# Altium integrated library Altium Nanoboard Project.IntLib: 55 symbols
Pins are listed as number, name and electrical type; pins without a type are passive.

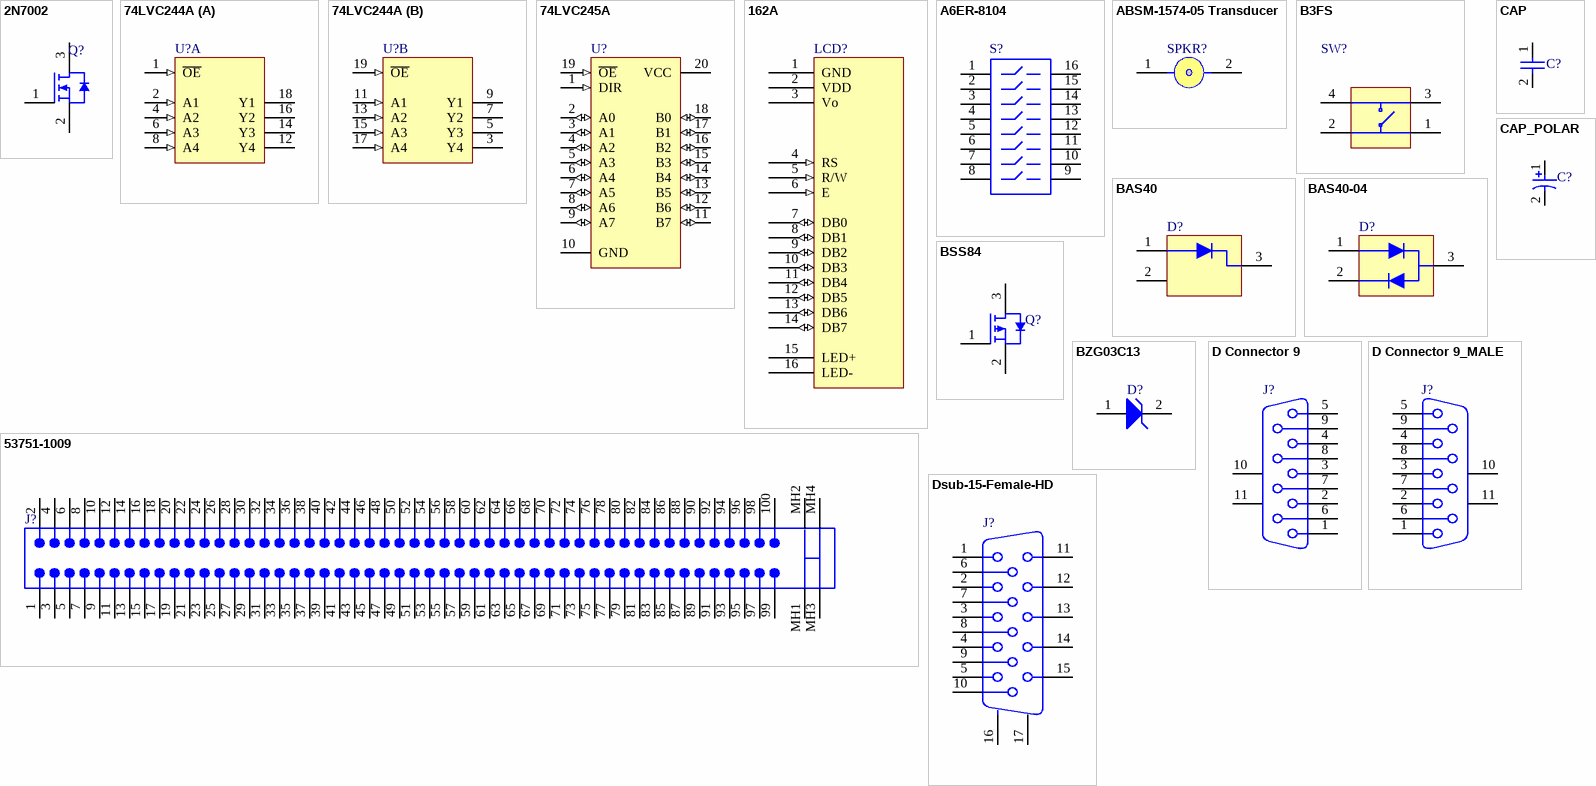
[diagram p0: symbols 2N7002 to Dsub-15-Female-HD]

## 2N7002
designator Q?
N-Channel Enhancement Mode FET
footprint SO-G3 (SOT-23; 3 Leads; 1.9mm x 2.2 mm (LxW))
pcadlib SO-G3 (SOT-23; 3 Leads; 1.9mm x 2.2 mm (LxW))
pins: 1 G "Gate", 2 S "Source", 3 D "Drain"

## 74LVC244A
designator U?
Octal Buffer/Driver with 3-State Outputs
footprint SSO-G20/P.65 (SSOP; 20 Leads; Body Width 5.3 mm; Pitch 0.65 mm)
pcadlib SSO-G20/P.65 (SSOP; 20 Leads; Body Width 5.3 mm; Pitch 0.65 mm)
pins on every part: 10 GND (power) hidden to GND, 20 VCC (power) hidden to VCC
part A pins: 1 ~{OE} (in), 2 A1 (in), 4 A2 (in), 6 A3 (in), 8 A4 (in), 12 Y4 (hiz), 14 Y3 (hiz), 16 Y2 (hiz), 18 Y1 (hiz)
part B pins: 3 Y4 (hiz), 5 Y3 (hiz), 7 Y2 (hiz), 9 Y1 (hiz), 11 A1 (in), 13 A2 (in), 15 A3 (in), 17 A4 (in), 19 ~{OE} (in)

## 74LVC245A
designator U?
Octal Bus Transceiver with 3-State Outputs
footprint SSO-G20/P.65 (SSOP; 20 Leads; Body Width 5.3 mm; Pitch 0.65 mm)
pcadlib SSO-G20/P.65 (SSOP; 20 Leads; Body Width 5.3 mm; Pitch 0.65 mm)
pins: 1 DIR (in), 2 A0 (io), 3 A1 (io), 4 A2 (io), 5 A3 (io), 6 A4 (io), 7 A5 (io), 8 A6 (io), 9 A7 (io), 10 GND (power), 11 B7 (io), 12 B6 (io), 13 B5 (io), 14 B4 (io), 15 B3 (io), 16 B2 (io), 17 B1 (io), 18 B0 (io), 19 ~{OE} (in), 20 VCC (power)

## 162A
designator LCD?
16 char * 2 line LCD character display with b/light
footprint 162A (Displaytronic, ACM 1602K Series, LCD Module)
pcadlib 162A (Displaytronic, ACM 1602K Series, LCD Module)
pins: 1 GND (power) "VSS - 0V", 2 VDD (power) "VDD - 5V", 3 Vo (hiz) "Input Voltage For LCD", 4 RS (in) "H = Data Signal, L = Instrunction Signal", 5 R/W (in) "H = Read Mode, L = Write Mode", 6 E (in) "Chip Enable (H, H->L)", 7 DB0 (io) "Chip Enable (H, H->L)", 8 DB1 (io) "Chip Enable (H, H->L)", 9 DB2 (io) "Chip Enable (H, H->L)", 10 DB3 (io) "Chip Enable (H, H->L)", 11 DB4 (io) "Chip Enable (H, H->L)", 12 DB5 (io) "Chip Enable (H, H->L)", 13 DB6 (io) "Chip Enable (H, H->L)", 14 DB7 (io) "Chip Enable (H, H->L)", 15 LED+ (power) "LED Backlight +", 16 LED- (power) "LED Backlight -"

## 53751-1009
designator J?
Board-to-Board, Docking Station, 0.80mm (.031") Pitch, Shielded Plug, Vertical, Ultra Low Profile, SMT
footprint 53751 (Board-to-Board, Docking Station, 0.80mm (.031") Pitch, Shielded Plug, Vertical, Ultra Low Profile, SMT)
pcadlib 53751 (Board-to-Board, Docking Station, 0.80mm (.031") Pitch, Shielded Plug, Vertical, Ultra Low Profile, SMT)
pins: 1, 2, 3, 4, 5, 6, 7, 8, 9, 10, 11, 12, 13, 14, 15, 16, 17, 18, 19, 20, 21, 22, 23, 24, 25, 26, 27, 28, 29, 30, 31, 32, 33, 34, 35, 36, 37, 38, 39, 40, 41, 42, 43, 44, 45, 46, 47, 48, 49, 50, 51, 52, 53, 54, 55, 56, 57, 58, 59, 60, 61, 62, 63, 64, 65, 66, 67, 68, 69, 70, 71, 72, 73, 74, 75, 76, 77, 78, 79, 80, 81, 82, 83, 84, 85, 86, 87, 88, 89, 90, 91, 92, 93, 94, 95, 96, 97, 98, 99, 100, MH1, MH2, MH2A, MH2B, MH3, MH4, MH4A, MH4B
1 alternate drawing of the same symbol

## A6ER-8104
designator S?
4009 Series DIP Switch, Raised actuator
footprint DIP-16-KEY (DIP; 16 Leads; Row Spacing 7.62 mm; Pitch 2.54 mm)
pcadlib DIP-16-KEY (DIP; 16 Leads; Row Spacing 7.62 mm; Pitch 2.54 mm)
pins: 1, 2, 3, 4, 5, 6, 7, 8, 9, 10, 11, 12, 13, 14, 15, 16

## ABSM-1574-05 Transducer
designator SPKR?
Magnetic transducer Buzzer
footprint ABSM-1574 (Surface Mount Magnetic Buzzer; Body 12.8 x 12.8 mm (LxW))
pcadlib ABSM-1574 (Surface Mount Magnetic Buzzer; Body 12.8 x 12.8 mm (LxW))
pins: 1, 1A, 2, 2A

## B3FS
designator SW?
SPNA SMD Keyboard Switch (TACT Switch)
footprint B3FS_SWITCH (Surface Mount DTSM Tact Switch; Body 6 x 6 mm (LxW))
pcadlib B3FS_SWITCH (Surface Mount DTSM Tact Switch; Body 6 x 6 mm (LxW))
pins: 1, 2, 3, 4

## BAS40
designator D?
Schottky Diode
footprint SO-G3 (SOT-23; 3 Leads; 1.9mm x 2.2 mm (LxW))
pcadlib SO-G3 (SOT-23; 3 Leads; 1.9mm x 2.2 mm (LxW))
pins: 1, 2, 3

## BAS40-04
designator D?
Dual Schottky Diode, series connected
footprint SO-G3 (SOT-23; 3 Leads; 1.9mm x 2.2 mm (LxW))
pcadlib SO-G3 (SOT-23; 3 Leads; 1.9mm x 2.2 mm (LxW))
pins: 1, 2, 3

## BSS84
designator Q?
P-Channel Enhancement Mode FET
footprint SO-G3 (SOT-23; 3 Leads; 1.9mm x 2.2 mm (LxW))
pcadlib SO-G3 (SOT-23; 3 Leads; 1.9mm x 2.2 mm (LxW))
pins: 1 G "Gate", 2 S "Source", 3 D "Drain"

## BZG03C13
designator D?
Zener Diode, 6.2V, 5W
footprint DO214 (2 C-Bend Leads; Body 4.3 x 3.6 mm (LxW))
pcadlib DO214 (2 C-Bend Leads; Body 4.3 x 3.6 mm (LxW))
pins: 1 A, 2 K

## CAP
designator C?
Capacitor, Multi Layer Ceramic
footprint CC2012-0805 (Surface Mount Capacitor; 0805 Case Size)
pcadlib CC2012-0805 (Surface Mount Capacitor; 0805 Case Size)
pins: 1, 2

## CAP_POLAR
designator C?
Capacitor, Tantalum
footprint MCCT-B (Surface Mount Chip Capacitor; Tantalum; 1.9mm x 2.2 mm (LxW))
pcadlib MCCT-B (Surface Mount Chip Capacitor; Tantalum; 1.9mm x 2.2 mm (LxW))
pins: 1, 2

## D Connector 9
designator J?
7906 Series DSUB Right Angle Socket Assembly, 9 Positions
footprint DSUB1.385-2H9 (7906 Series DSUB Right Angle Socket; Body Width, 30.81mm, 9 Positions)
pcadlib DSUB1.385-2H9 (7906 Series DSUB Right Angle Socket; Body Width, 30.81mm, 9 Positions)
pins: 1, 2, 3, 4, 5, 6, 7, 8, 9, 10 MH1, 11 MH2

## D Connector 9_MALE
designator J?
7906 Series DSUB Right Angle Plug Assembly, 9 Positions
footprint DSUB1.9_MALE (7906 Series DSUB Right Angle Plug; Body Width, 30.81mm, 9 Positions)
pcadlib DSUB1.9_MALE (7906 Series DSUB Right Angle Plug; Body Width, 30.81mm, 9 Positions)
pins: 1, 2, 3, 4, 5, 6, 7, 8, 9, 10 MH1, 11 MH2

## Dsub-15-Female-HD
designator J?
7915 Series Dsub-15 High density VGA Female connector
footprint DB15-VGA-Female (7915 Series DSUB Right Angle VGA Female connector; Body Width, 30.81mm, 15 Positions)
pcadlib DB15-VGA-Female (7915 Series DSUB Right Angle VGA Female connector; Body Width, 30.81mm, 15 Positions)
pins: 1 "Red Video", 2 "Green Video", 3 "Blue Video", 4 "Monitor ID Bit 2 (Ground)", 5 (power) "Ground", 6 (power) "Red Return (Ground)", 7 (power) "Green Return (Ground)", 8 (power) "Blue Return (Ground)", 9 "Key (not used)", 10 (power) "Sync Return (Ground)", 11 (power) "Monitor ID Bit 0 (Ground)", 12 "Monitor ID Bit 1 (Not Used)", 13 "Horizontal Zync", 14 "Vertical Sync", 15 "Vertical Sync", 16 MH1 "shield", 17 MH2 "shield"

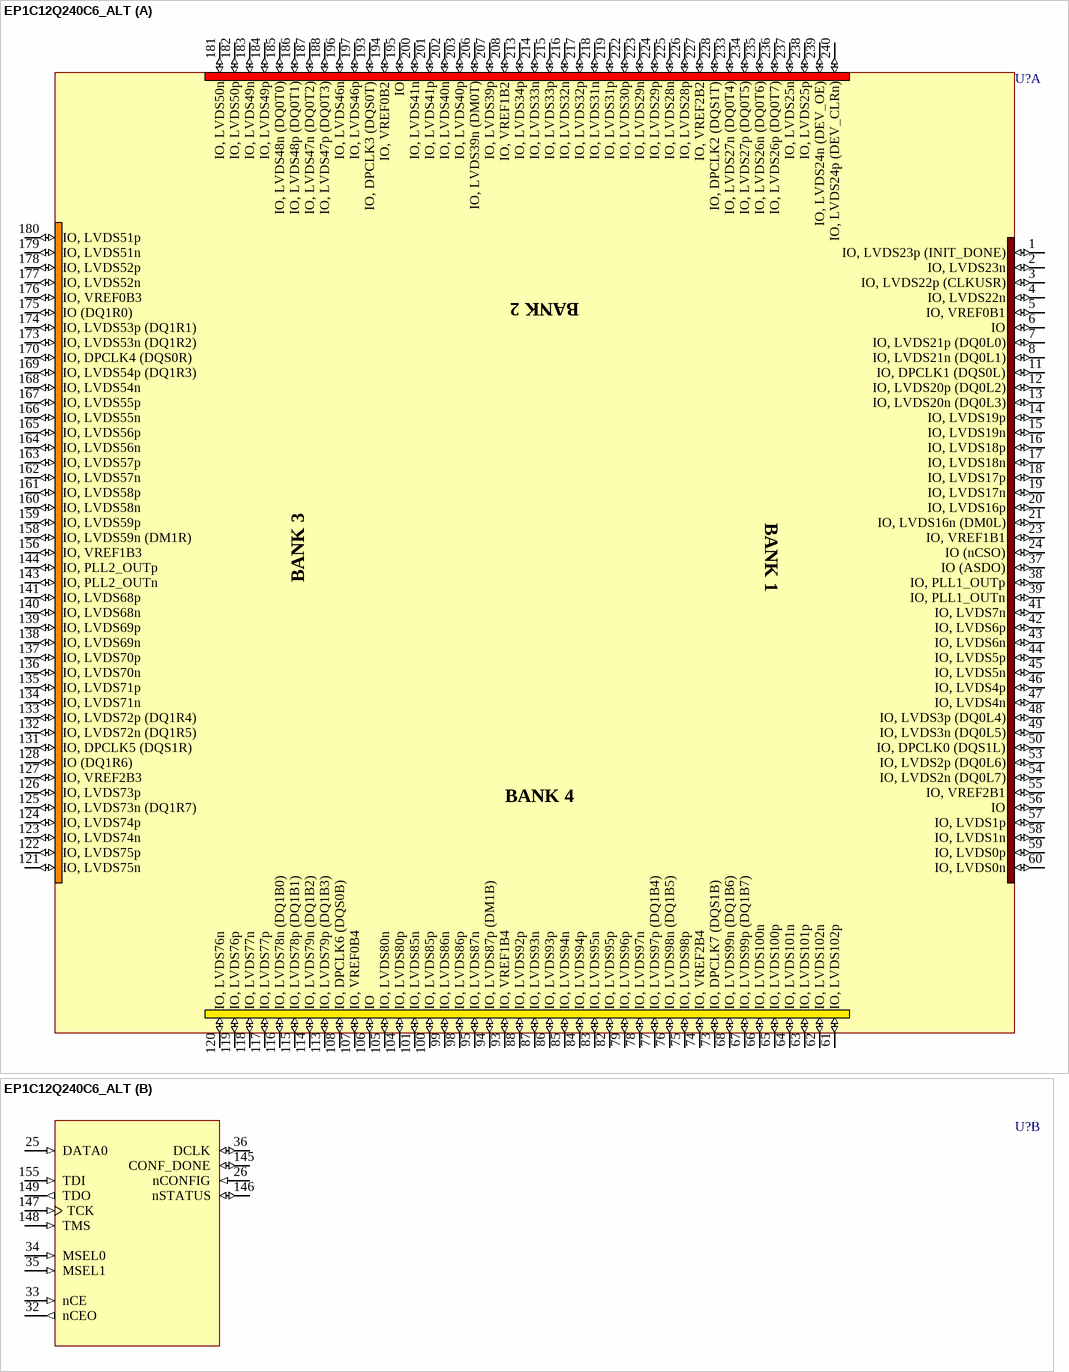
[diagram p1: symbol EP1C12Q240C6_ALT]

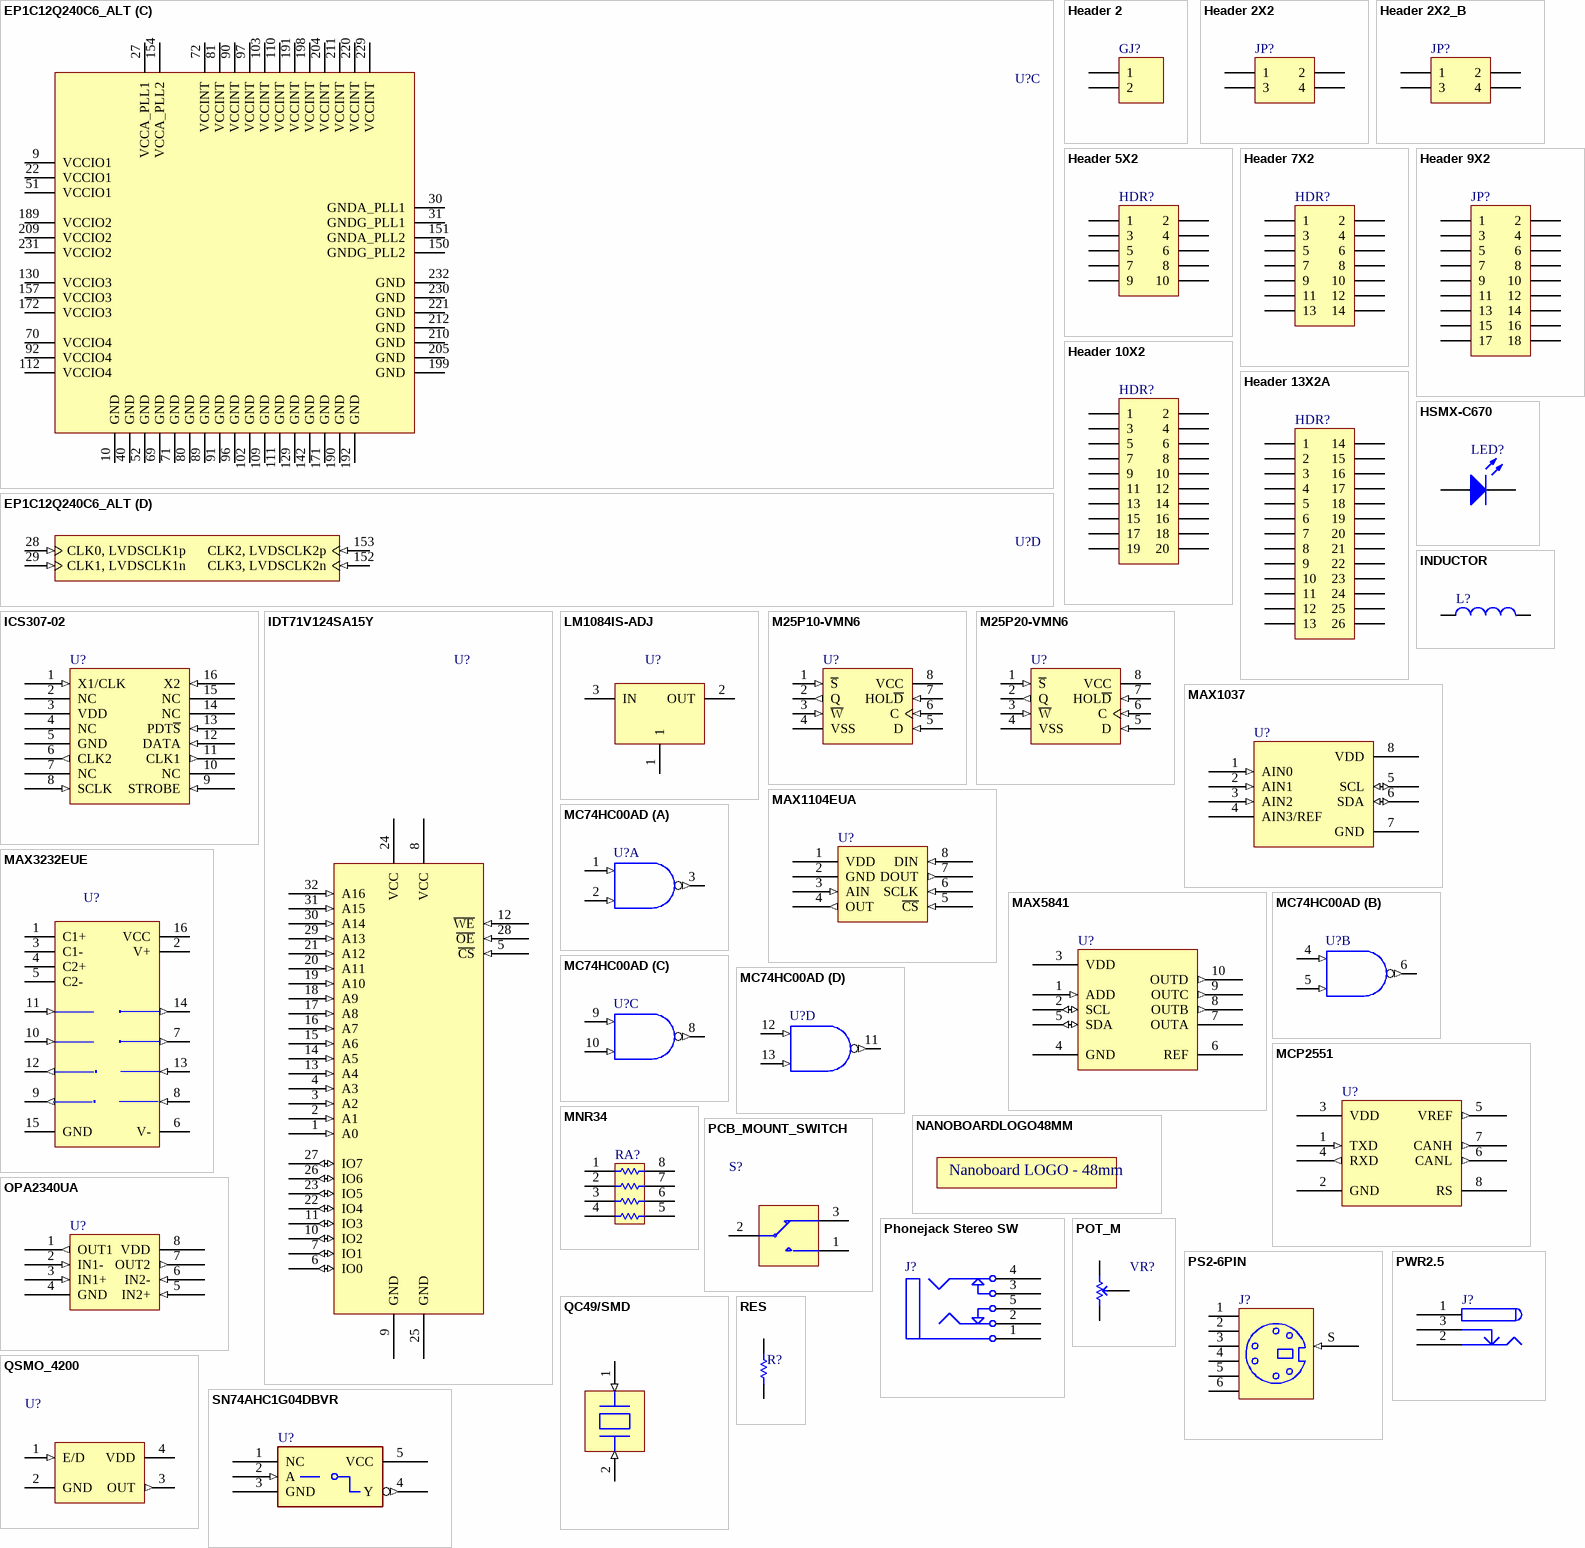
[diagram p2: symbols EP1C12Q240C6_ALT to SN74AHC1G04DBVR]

## EP1C12Q240C6_ALT
designator U?
Cyclone Family, 1.5V FPGA, 173 I/O Pins, 2 x PLLs, Commercial Grade, Speed Grade 6; PackageDocument: ver11.0, Feb-2003; Note: EP1C12Q240C6 in our IntLibs
footprint F-QFP32X32-G240/P.5N(RS) (240-Pin Plastic Quad Flat Pack (PQFP))
pcadlib F-QFP32X32-G240/P.5N(RS) (240-Pin Plastic Quad Flat Pack (PQFP))
3D model EP1C12-PQFP240 (240-Pin Plastic Quad Flat Pack (PQFP))
signal-integrity model 1c (Cyclone)
part A pins: 1 IO, LVDS23p (INIT_DONE) (io), 2 IO, LVDS23n (io), 3 IO, LVDS22p (CLKUSR) (io), 4 IO, LVDS22n (io), 5 IO, VREF0B1 (io), 6 IO (io), 7 IO, LVDS21p (DQ0L0) (io), 8 IO, LVDS21n (DQ0L1) (io), 11 IO, DPCLK1 (DQS0L) (io), 12 IO, LVDS20p (DQ0L2) (io), 13 IO, LVDS20n (DQ0L3) (io), 14 IO, LVDS19p (io), 15 IO, LVDS19n (io), 16 IO, LVDS18p (io), 17 IO, LVDS18n (io), 18 IO, LVDS17p (io), 19 IO, LVDS17n (io), 20 IO, LVDS16p (io), 21 IO, LVDS16n (DM0L) (io), 23 IO, VREF1B1 (io), 24 IO (nCSO) (io), 37 IO (ASDO) (io), 38 IO, PLL1_OUTp (io), 39 IO, PLL1_OUTn (io), 41 IO, LVDS7n (io), 42 IO, LVDS6p (io), 43 IO, LVDS6n (io), 44 IO, LVDS5p (io), 45 IO, LVDS5n (io), 46 IO, LVDS4p (io), 47 IO, LVDS4n (io), 48 IO, LVDS3p (DQ0L4) (io), 49 IO, LVDS3n (DQ0L5) (io), 50 IO, DPCLK0 (DQS1L) (io), 53 IO, LVDS2p (DQ0L6) (io), 54 IO, LVDS2n (DQ0L7) (io), 55 IO, VREF2B1 (io), 56 IO (io), 57 IO, LVDS1p (io), 58 IO, LVDS1n (io), 59 IO, LVDS0p (io), 60 IO, LVDS0n (io), 61 IO, LVDS102p (io), 62 IO, LVDS102n (io), 63 IO, LVDS101p (io), 64 IO, LVDS101n (io), 65 IO, LVDS100p (io), 66 IO, LVDS100n (io), 67 IO, LVDS99p (DQ1B7) (io), 68 IO, LVDS99n (DQ1B6) (io), 73 IO, DPCLK7 (DQS1B) (io), 74 IO, VREF2B4 (io), 75 IO, LVDS98p (io), 76 IO, LVDS98n (DQ1B5) (io), 77 IO, LVDS97p (DQ1B4) (io), 78 IO, LVDS97n (io), 79 IO, LVDS96p (io), 82 IO, LVDS95p (io), 83 IO, LVDS95n (io), 84 IO, LVDS94p (io), 85 IO, LVDS94n (io), 86 IO, LVDS93p (io), 87 IO, LVDS93n (io), 88 IO, LVDS92p (io), 93 IO, VREF1B4 (io), 94 IO, LVDS87p (DM1B) (io), 95 IO, LVDS87n (io), 98 IO, LVDS86p (io), 99 IO, LVDS86n (io), 100 IO, LVDS85p (io), 101 IO, LVDS85n (io), 104 IO, LVDS80p (io), 105 IO, LVDS80n (io), 106 IO (io), 107 IO, VREF0B4 (io), 108 IO, DPCLK6 (DQS0B) (io), 113 IO, LVDS79p (DQ1B3) (io), 114 IO, LVDS79n (DQ1B2) (io), 115 IO, LVDS78p (DQ1B1) (io), 116 IO, LVDS78n (DQ1B0) (io), 117 IO, LVDS77p (io), 118 IO, LVDS77n (io), 119 IO, LVDS76p (io), 120 IO, LVDS76n (io), 121 IO, LVDS75n (io), 122 IO, LVDS75p (io), 123 IO, LVDS74n (io), 124 IO, LVDS74p (io), 125 IO, LVDS73n (DQ1R7) (io), 126 IO, LVDS73p (io), 127 IO, VREF2B3 (io), 128 IO (DQ1R6) (io), 131 IO, DPCLK5 (DQS1R) (io), 132 IO, LVDS72n (DQ1R5) (io), 133 IO, LVDS72p (DQ1R4) (io), 134 IO, LVDS71n (io), 135 IO, LVDS71p (io), 136 IO, LVDS70n (io), 137 IO, LVDS70p (io), 138 IO, LVDS69n (io), 139 IO, LVDS69p (io), 140 IO, LVDS68n (io), 141 IO, LVDS68p (io), 143 IO, PLL2_OUTn (io), 144 IO, PLL2_OUTp (io), 156 IO, VREF1B3 (io), 158 IO, LVDS59n (DM1R) (io), 159 IO, LVDS59p (io), 160 IO, LVDS58n (io), 161 IO, LVDS58p (io), 162 IO, LVDS57n (io), 163 IO, LVDS57p (io), 164 IO, LVDS56n (io), 165 IO, LVDS56p (io), 166 IO, LVDS55n (io), 167 IO, LVDS55p (io), 168 IO, LVDS54n (io), 169 IO, LVDS54p (DQ1R3) (io), 170 IO, DPCLK4 (DQS0R) (io), 173 IO, LVDS53n (DQ1R2) (io), 174 IO, LVDS53p (DQ1R1) (io), 175 IO (DQ1R0) (io), 176 IO, VREF0B3 (io), 177 IO, LVDS52n (io), 178 IO, LVDS52p (io), 179 IO, LVDS51n (io), 180 IO, LVDS51p (io), 181 IO, LVDS50n (io), 182 IO, LVDS50p (io), 183 IO, LVDS49n (io), 184 IO, LVDS49p (io), 185 IO, LVDS48n (DQ0T0) (io), 186 IO, LVDS48p (DQ0T1) (io), 187 IO, LVDS47n (DQ0T2) (io), 188 IO, LVDS47p (DQ0T3) (io), 193 IO, DPCLK3 (DQS0T) (io), 194 IO, VREF0B2 (io), 195 IO (io), 196 IO, LVDS46n (io), 197 IO, LVDS46p (io), 200 IO, LVDS41n (io), 201 IO, LVDS41p (io), 202 IO, LVDS40n (io), 203 IO, LVDS40p (io), 206 IO, LVDS39n (DM0T) (io), 207 IO, LVDS39p (io), 208 IO, VREF1B2 (io), 213 IO, LVDS34p (io), 214 IO, LVDS33n (io), 215 IO, LVDS33p (io), 216 IO, LVDS32n (io), 217 IO, LVDS32p (io), 218 IO, LVDS31n (io), 219 IO, LVDS31p (io), 222 IO, LVDS30p (io), 223 IO, LVDS29n (io), 224 IO, LVDS29p (io), 225 IO, LVDS28n (io), 226 IO, LVDS28p (io), 227 IO, VREF2B2 (io), 228 IO, DPCLK2 (DQS1T) (io), 233 IO, LVDS27n (DQ0T4) (io), 234 IO, LVDS27p (DQ0T5) (io), 235 IO, LVDS26n (DQ0T6) (io), 236 IO, LVDS26p (DQ0T7) (io), 237 IO, LVDS25n (io), 238 IO, LVDS25p (io), 239 IO, LVDS24n (DEV_OE) (io), 240 IO, LVDS24p (DEV_CLRn) (io)
part B pins: 25 DATA0 (in), 26 nCONFIG (in), 32 nCEO (out), 33 nCE (in), 34 MSEL0 (in), 35 MSEL1 (in), 36 DCLK (io), 145 CONF_DONE (io), 146 nSTATUS (io), 147 TCK (in), 148 TMS (in), 149 TDO (out), 155 TDI (in)
part C pins: 9 VCCIO1 (power), 10 GND (power), 22 VCCIO1 (power), 27 VCCA_PLL1 (power), 30 GNDA_PLL1 (power), 31 GNDG_PLL1 (power), 40 GND (power), 51 VCCIO1 (power), 52 GND (power), 69 GND (power), 70 VCCIO4 (power), 71 GND (power), 72 VCCINT (power), 80 GND (power), 81 VCCINT (power), 89 GND (power), 90 VCCINT (power), 91 GND (power), 92 VCCIO4 (power), 96 GND (power), 97 VCCINT (power), 102 GND (power), 103 VCCINT (power), 109 GND (power), 110 VCCINT (power), 111 GND (power), 112 VCCIO4 (power), 129 GND (power), 130 VCCIO3 (power), 142 GND (power), 150 GNDG_PLL2 (power), 151 GNDA_PLL2 (power), 154 VCCA_PLL2 (power), 157 VCCIO3 (power), 171 GND (power), 172 VCCIO3 (power), 189 VCCIO2 (power), 190 GND (power), 191 VCCINT (power), 192 GND (power), 198 VCCINT (power), 199 GND (power), 204 VCCINT (power), 205 GND (power), 209 VCCIO2 (power), 210 GND (power), 211 VCCINT (power), 212 GND (power), 220 VCCINT (power), 221 GND (power), 229 VCCINT (power), 230 GND (power), 231 VCCIO2 (power), 232 GND (power)
part D pins: 28 CLK0, LVDSCLK1p (in), 29 CLK1, LVDSCLK1n (in), 152 CLK3, LVDSCLK2n (in), 153 CLK2, LVDSCLK2p (in)

## Header 2
designator GJ?
2011 Series Header, 2 Pins, 2.54mm pitch
footprint HDR1X2 (2011 Series Header, 2 Pins, 2.54mm Pitch)
pcadlib HDR1X2 (2011 Series Header, 2 Pins, 2.54mm Pitch)
pins: 1, 2

## Header 2X2
designator JP?
2011 Series Header, 4 Pins, Dual row, 2.54mil pitch
footprint HDR2X2 (2011 Series Header, 4 Pins, Dual Row, 2.54mm Pitch)
pcadlib HDR2X2 (2011 Series Header, 4 Pins, Dual Row, 2.54mm Pitch)
pins: 1, 2, 3, 4

## Header 2X2_B
designator JP?
2011 Series Header, 4 Pins, Dual row, 2.54mil pitch
footprint HDR2X2_B (2011 Series Header, 4 Pins, Dual Row, 2.54mm Pitch)
pcadlib HDR2X2_B (2011 Series Header, 4 Pins, Dual Row, 2.54mm Pitch)
pins: 1, 2, 3, 4

## Header 5X2
designator HDR?
2011 Series Header, 10 Pins, Dual row, 2.54mm pitch
footprint HDR2X5 (2011 Series Header, 10 Pins, Dual Row, 2.54mm Pitch)
pcadlib HDR2X5 (2011 Series Header, 10 Pins, Dual Row, 2.54mm Pitch)
pins: 1, 2, 3, 4, 5, 6, 7, 8, 9, 10

## Header 7X2
designator HDR?
2011 Series Header, 14 Pins, Dual row, 2.54mm pitch
footprint HDR2X7 (2011 Series Header, 14 Pins, Dual Row, 2.54mm Pitch)
pcadlib HDR2X7 (2011 Series Header, 14 Pins, Dual Row, 2.54mm Pitch)
pins: 1, 2, 3, 4, 5, 6, 7, 8, 9, 10, 11, 12, 13, 14

## Header 9X2
designator JP?
2011 Series Header, 18 Pins, Dual row, 2.54mm pitch
footprint HDR2X9 (2011 Series Header, 18 Pins, Dual Row, 2.54mm Pitch)
pcadlib HDR2X9 (2011 Series Header, 18 Pins, Dual Row, 2.54mm Pitch)
pins: 1, 2, 3, 4, 5, 6, 7, 8, 9, 10, 11, 12, 13, 14, 15, 16, 17, 18

## Header 10X2
designator HDR?
2011 Series Header, 20 Pins, Dual row, 2.54mm pitch
footprint HDR2X10 (2011 Series Header, 20 Pins, Dual Row, 2.54mm Pitch)
pcadlib HDR2X10 (2011 Series Header, 20 Pins, Dual Row, 2.54mm Pitch)
pins: 1, 2, 3, 4, 5, 6, 7, 8, 9, 10, 11, 12, 13, 14, 15, 16, 17, 18, 19, 20

## Header 13X2A
designator HDR?
3012 Series Box Header, 26 Pins, Dual Row, 2.54mm pitch, Low Profile Vertical
footprint HDR2X13_CEN_LP (3012 Series Box Header, 26 Pins, Dual Row, 2.54mm Pitch)
pcadlib HDR2X13_CEN_LP (3012 Series Box Header, 26 Pins, Dual Row, 2.54mm Pitch)
pins: 1, 2, 3, 4, 5, 6, 7, 8, 9, 10, 11, 12, 13, 14, 15, 16, 17, 18, 19, 20, 21, 22, 23, 24, 25, 26

## HSMX-C670
designator LED?
RED AS AlGaAs SMD LED
footprint SMD _LED (RED AS AlGaAs SMD LED, Body; 2mm x 1.25 mm (LxW))
pcadlib SMD _LED (RED AS AlGaAs SMD LED, Body; 2mm x 1.25 mm (LxW))
pins: 1 A, 2 K

## ICS307-02
designator U?
Serially Programmable Clock Source
footprint SO-G16 (Small Outline; 16 Leads; Body Width 3.5 mm; Pitch 1.27 mm)
pcadlib SO-G16 (Small Outline; 16 Leads; Body Width 3.5 mm; Pitch 1.27 mm)
pins: 1 X1/CLK (in) "Reference Word Devider Input", 2 NC "Reference Word Devider Input", 3 VDD (power) "Positive Supply, 3V3 or 5V", 4 NC, 5 GND (power), 6 CLK2 (out) "Fixed Clock Ref", 7 NC "Crystal connection", 8 SCLK (in) "Serial Programming Clock", 9 STROBE (in) "Serial Programming Strobe", 10 NC, 11 CLK1 (out) "Variable Clock Output", 12 DATA (in) "Serial Programming Data", 13 PDT~{S} (in) "Low = TriState CLK1 and CLK2 and Power Down", 14 NC, 15 NC, 16 X2 (in) "Crystal Terminal"

## IDT71V124SA15Y
designator U?
CMOS Static RAM, 3.3V, 128K x 8 bit
footprint SO-J32 (SOJ; 32 Leads; Body Width 7.5 mm; Pitch 1.27 mm)
pcadlib SO-J32 (SOJ; 32 Leads; Body Width 7.5 mm; Pitch 1.27 mm)
pins: 1 A0 (in) "Address 0", 2 A1 (in) "Address 1", 3 A2 (in) "Address 3", 4 A3 (in) "Address 3", 5 ~{CS} (in) "Chip Select", 6 IO0 (io) "Data 0", 7 IO1 (io) "Data 1", 8 VCC (power) "Pos Supply", 9 GND (power), 10 IO2 (io) "Data 2", 11 IO3 (io) "Data 3", 12 ~{WE} (in) "Write Enable", 13 A4 (in) "Address 4", 14 A5 (in) "Address 5", 15 A6 (in) "Address 6", 16 A7 (in) "Address 7", 17 A8 (in) "Address 8", 18 A9 (in) "Address 9", 19 A10 (in) "Address 10", 20 A11 (in) "Address 11", 21 A12 (in) "Address 12", 22 IO4 (io) "Data 4", 23 IO5 (io) "Data 5", 24 VCC (power) "Pos Supply", 25 GND (power), 26 IO6 (io) "Data 6", 27 IO7 (io) "Data 7", 28 ~{OE} (in) "Output Enable", 29 A13 (in) "Address 13", 30 A14 (in) "Address 14", 31 A15 (in) "Address 15", 32 A16 (in) "Address 16"

## INDUCTOR
designator L?
CM453232 Series Wirewound Inductor, 330uH
footprint CC4532-1812 (Surface Mount Chip Inductor; 4mm x 3.4 mm (LxW))
pcadlib CC4532-1812 (Surface Mount Chip Inductor; 4mm x 3.4 mm (LxW))
pins: 1, 2

## LM1084IS-ADJ
designator U?
5A Low Dropout Positive Regulators
footprint TO-263 (TO-263-AB; 3 Leads (1 Cropped); Body 14.35 (inc. leads) x 10.41 mm (LxW max))
pcadlib TO-263 (TO-263-AB; 3 Leads (1 Cropped); Body 14.35 (inc. leads) x 10.41 mm (LxW max))
pins: 1 "Output", 2 OUT (power) "Output", 3 IN (power) "Input"

## M25P10-VMN6
designator U?
8 Mbit, Low Voltage, Serial Flash Memory With 40 MHz SPI Bus Interface
footprint SO8_MW/SO8_MN (Small Outline; 8 Leads; Body Width 5.2 mm; Pitch 1.27 mm)
pcadlib SO8_MW/SO8_MN (Small Outline; 8 Leads; Body Width 5.2 mm; Pitch 1.27 mm)
pins: 1 ~{S} (in), 2 Q (out) "Serial Output", 3 ~{W} (in) "Serial Output", 4 VSS (power) "Serial Output", 5 D (in) "Serial Input", 6 C (in) "Serial Input", 7 HOL~{D} (in) "Serial Input", 8 VCC (power) "Serial Input"

## M25P20-VMN6
designator U?
8 Mbit, Low Voltage, Serial Flash Memory With 40 MHz SPI Bus Interface
footprint SO8_MW/SO8_MN (Small Outline; 8 Leads; Body Width 5.2 mm; Pitch 1.27 mm)
pcadlib SO8_MW/SO8_MN (Small Outline; 8 Leads; Body Width 5.2 mm; Pitch 1.27 mm)
pins: 1 ~{S} (in), 2 Q (out) "Serial Output", 3 ~{W} (in) "Serial Output", 4 VSS (power) "Serial Output", 5 D (in) "Serial Input", 6 C (in) "Serial Input", 7 HOL~{D} (in) "Serial Input", 8 VCC (power) "Serial Input"

## MAX1037
designator U?
4 Channel 8 Bit ADC, I2C interface, 2.7V to 3.6V Supply
footprint SOT23_8 (Small Outline; 8 Leads; Body 2.9 x 1.6 mm (LxW max))
pcadlib SOT23_8 (Small Outline; 8 Leads; Body 2.9 x 1.6 mm (LxW max))
pins: 1 AIN0 (in) "Analog Input 0", 2 AIN1 (in) "Analog Input 0", 3 AIN2 (in) "Analog Input 0", 4 AIN3/REF (power) "Analog Input 3/ Reference Input", 5 SCL (io) "I2C Clock Line", 6 SDA (io) "I2C Data Line", 7 GND (power), 8 VDD (power) "Positive Supply"

## MAX1104EUA
designator U?
8 bit CODEC with 4 wire logic interface
footprint TSSO3x5-G8/X.35 (Shrink Small Outline; 8 Leads; Body Width 3 mm; Pitch 0.65 mm)
pcadlib TSSO3x5-G8/X.35 (Shrink Small Outline; 8 Leads; Body Width 3 mm; Pitch 0.65 mm)
pins: 1 VDD (power) "Positive Supply 2V7 5V5", 2 GND (power), 3 AIN (in) "Analog Input", 4 OUT (out) "Analog Output", 5 ~{CS} (in) "Chip Select", 6 SCLK (in) "Serial Clock", 7 DOUT (out) "Serial Output", 8 DIN (in) "SPI Serial Input"

## MAX3232EUE
designator U?
3.0V TO 5.5V, Low-Power, up to 1Mbps, True RS-232 Transceiver Using Four 0.1µF External Capacitor
footprint SO-G16 (Small Outline; 16 Leads; Body Width 3.9 mm; Pitch 1.27 mm)
pcadlib SO-G16 (Small Outline; 16 Leads; Body Width 3.9 mm; Pitch 1.27 mm)
pins: 1 C1+, 2 V+ (power), 3 C1-, 4 C2+, 5 C2-, 6 V- (power), 7 T2OUT (out), 8 R2IN (in), 9 R2OUT (out), 10 T2IN (in), 11 T1IN (in), 12 R1OUT (out), 13 R1IN (in), 14 T1OUT (out), 15 GND (power), 16 VCC (power)

## MAX5841
designator U?
4 Channel DAC, I2C, 2.7V to 5.5V
footprint USOP10 (Shrink Small Outline; 10 Leads; Body Width 3 mm; Pitch 0.5 mm)
pcadlib USOP10 (Shrink Small Outline; 10 Leads; Body Width 3 mm; Pitch 0.5 mm)
pins: 1 ADD (in) "I2C Address Select", 2 SCL (io) "I2C Clock", 3 VDD (power) "Positive Supply 2.7V to 5.5V", 4 GND (power), 5 SDA (io) "GND", 6 REF "Reference Voltage Input 1V to VDD", 7 OUTA "DAC Output", 8 OUTB (out) "DAC Output", 9 OUTC (out) "DAC Output", 10 OUTD (out) "DAC Output"

## MC74HC00AD
designator U?
Quad 2-Input NAND Gate
footprint SO-G14/Y2.2 (Small Outline; 14 Leads; Body Width 3.9 mm; Pitch 1.27 mm)
pcadlib SO-G14/Y2.2 (Small Outline; 14 Leads; Body Width 3.9 mm; Pitch 1.27 mm)
pins on every part: 7 GND (power) hidden to GND, 14 VDD (power) hidden to VCC
part A pins: 1 A (in), 2 B (in), 3 Y (out)
part B pins: 4 A (in), 5 B (in), 6 Y (out)
part C pins: 8 Y (out), 9 A (in), 10 B (in)
part D pins: 11 Y (out), 12 A (in), 13 B (in)

## MCP2551
designator U?
High Speed Can Transceiver
footprint SOIC8 (Small Outline; 8 Leads; Body Width 3.9 mm; Pitch 1.27 mm)
pcadlib SOIC8 (Small Outline; 8 Leads; Body Width 3.9 mm; Pitch 1.27 mm)
pins: 1 TXD (in) "Screw Terminal", 2 GND (power), 3 VDD (power) "Positive Supply 4.5V to 5.5V", 4 RXD (out) "Receive Data", 5 VREF (out) "Reference Voltage", 6 CANL (out) "CAN Bus Low Line", 7 CANH (out) "CAN Bus High Line", 8 RS "Mode/Slope Setting"

## MNR34
designator RA?
Resistor Array, 8 pin, 4 Element, 100 Ohms
footprint MNR34 (Surface Mount, Chip Resistor Array; 5.2mm x 3.1 mm (LxW))
pcadlib MNR34 (Surface Mount, Chip Resistor Array; 5.2mm x 3.1 mm (LxW))
pins: 1, 2, 3, 4, 5, 6, 7, 8

## NANOBOARDLOGO48MM
designator ?  (graphical)
Altium Logo
footprint NanoBoard1_LOGO (NanoBoard Logo)
pcadlib NanoBoard1_LOGO (NanoBoard Logo)

## OPA2340UA
designator U?
Dual Operational Amplifier, Single-Supply, Rail-to-Rail
footprint SO-G8 (Small Outline; 8 Leads; Body Width 3.5 mm; Pitch 1.27 mm)
pcadlib SO-G8 (Small Outline; 8 Leads; Body Width 3.5 mm; Pitch 1.27 mm)
pins: 1 OUT1 (out), 2 IN1- (in), 3 IN1+ (in), 4 GND (power), 5 IN2+ (in), 6 IN2- (in), 7 OUT2 (out), 8 VDD (power)

## PCB_MOUNT_SWITCH
designator S?
SPDT Subminiature Toggle Switch, Right Angle Mounting, Vertical Actuation
footprint TL36WW15050 (SPDT Subminiature Toggle Switch, Right Angle Mounting, Vertical Actuation)
pcadlib TL36WW15050 (SPDT Subminiature Toggle Switch, Right Angle Mounting, Vertical Actuation)
pins: 1, 2, 3

## Phonejack Stereo SW
designator J?
3.5mm Audio Jack, Stereo
footprint ST-3150-5N (Stereo Jack, 3.5mm, 5 Position)
pcadlib ST-3150-5N (Stereo Jack, 3.5mm, 5 Position)
pins: 1, 1A, 1B, 2, 2A, 2B, 3, 3A, 3B, 4, 4A, 4B, 5, 5A, 5B

## POT_M
designator VR?
100k Ohms Square Trimming Potentiometer
footprint POT4MM-2 (Surface Mount, Square Trimming Potentiometer, Body 4.5mm x 4.5mm (LxW))
pcadlib POT4MM-2 (Surface Mount, Square Trimming Potentiometer, Body 4.5mm x 4.5mm (LxW))
pins: CCW -, CW +, W

## PS2-6PIN
designator J?
6 Pin Through Hole PS2 Socket (Kycon P/N)
footprint PS2-6PIN (PS2 Socket, 6 Pin, Through Hole)
pcadlib PS2-6PIN (PS2 Socket, 6 Pin, Through Hole)
pins: 1, 2, 3, 4, 5, 6, S (in)

## PWR2.5
designator J?
DC Power Jack, 2.5mm, KLD Series, PCB Mount
footprint KLD-0202 (DC Power Jack, 2.5mm, KLD Series, PCB Mount)
pcadlib KLD-0202 (DC Power Jack, 2.5mm, KLD Series, PCB Mount)
pins: 1 (power), 1A (power), 1B (power), 2 (power), 2A (power), 2B (power), 3 (power), 3A (power), 3B (power)

## QC49/SMD
designator CR?
Hy-Q QC49/SSMD Crystal, 20MHz
footprint QC49/SMD (Surface Mount 20MHz Crystal, 12.9mm x 4.8mm (LxW))
pcadlib QC49/SMD (Surface Mount 20MHz Crystal, 12.9mm x 4.8mm (LxW))
pins: 1 (in), 2 (in)

## QSMO_4200
designator U?
QSMO - 4200 SERIES, 40MHz, SURFACE MOUNT CRYSTAL OSCILLATOR
footprint QSMO_4200 (Surface Mount 40MHz Crystal, 7.5mm x 5mm (LxW))
pcadlib QSMO_4200 (Surface Mount 40MHz Crystal, 7.5mm x 5mm (LxW))
pins: 1 E/D (in) "Low Disables Clock", 2 GND (power), 3 OUT (out) "Output", 4 VDD (power)

## RES
designator R?
Resistor
footprint CC2012-0805 (Surface Mount Resistor; 0805 Case Size)
pcadlib CC2012-0805 (Surface Mount Resistor; 0805 Case Size)
pins: 1, 2

## SN74AHC1G04DBVR
designator U?
Single Gate Inverter
footprint SO-G5/P.95 (Small Outline; 5 Leads; Body 2 x 1.25 mm (LxW))
pcadlib SO-G5/P.95 (Small Outline; 5 Leads; Body 2 x 1.25 mm (LxW))
pins: 1 NC, 2 A (in), 3 GND (power), 4 Y (out), 5 VCC (power)

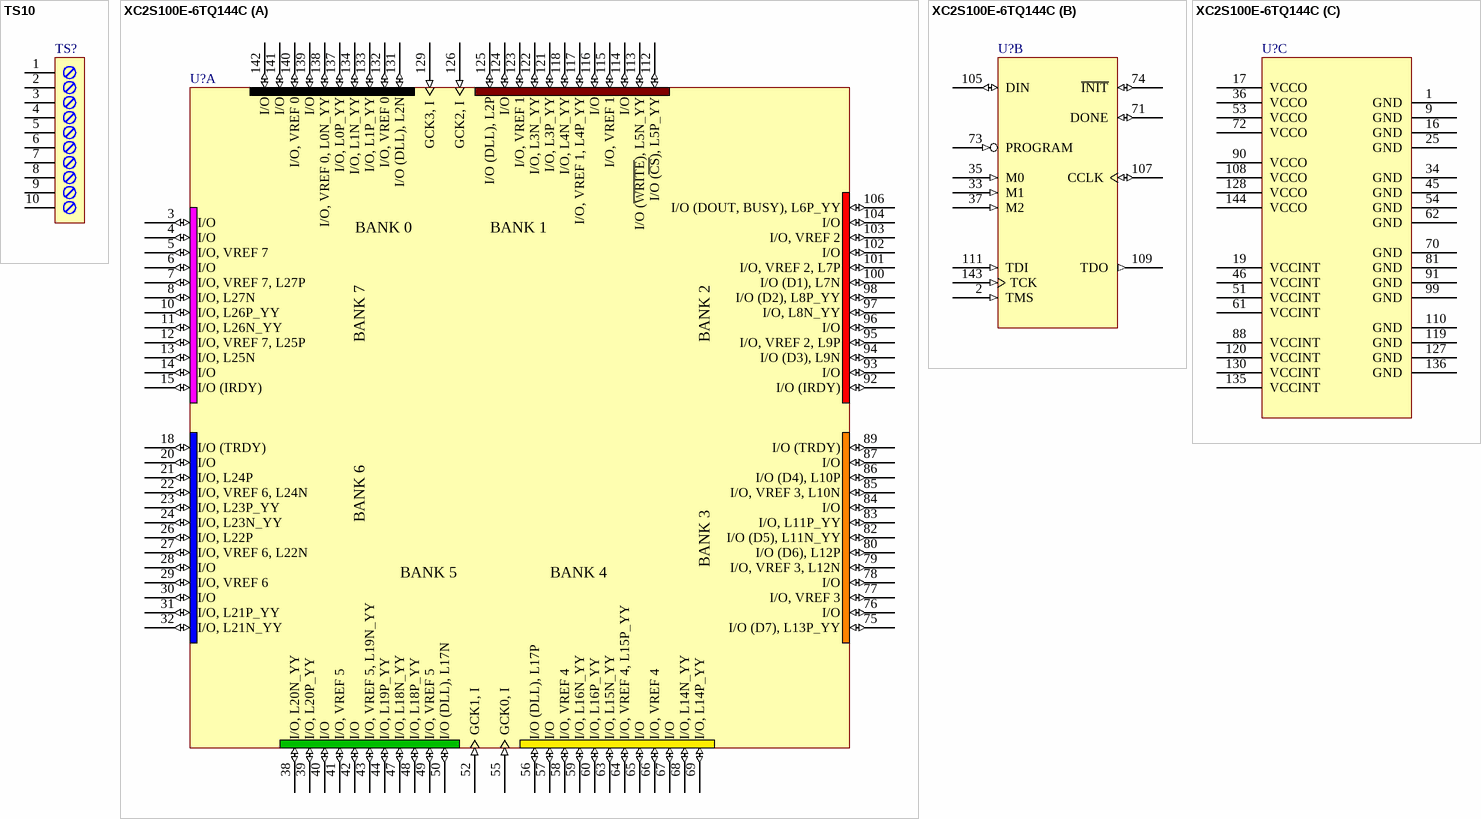
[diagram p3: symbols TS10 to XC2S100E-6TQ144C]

## TS10
designator TS?
Screw Terminal Strip, 10 Way, 2.54 mm Pitch
footprint TS2.54x10 (Screw Terminal Strip, 10 Way, 2.54 mm Pitch)
pcadlib TS2.54x10 (Screw Terminal Strip, 10 Way, 2.54 mm Pitch)
pins: 1 "Screw Terminal", 2 "Screw Terminal", 3 "Screw Terminal", 4 "Screw Terminal", 5 "Screw Terminal", 6 "Screw Terminal", 7 "Screw Terminal", 8 "Screw Terminal", 9 "Screw Terminal", 10 "Screw Terminal"

## XC2S100E-6TQ144C
designator U?
Spartan-IIE 1.8V FPGA, 144-Pin TQFP, Standard Performance, Commercial Grade
footprint TQ144 (144-Pin Thin Quad Flat Pack (TQ144))
pcadlib TQ144 (144-Pin Thin Quad Flat Pack (TQ144))
part A pins: 3 I/O (io), 4 I/O (io), 5 I/O, VREF 7 (io), 6 I/O (io), 7 I/O, VREF 7, L27P (io), 8 I/O, L27N (io), 10 I/O, L26P_YY (io), 11 I/O, L26N_YY (io), 12 I/O, VREF 7, L25P (io), 13 I/O, L25N (io), 14 I/O (io), 15 I/O (IRDY) (io), 18 I/O (TRDY) (io), 20 I/O (io), 21 I/O, L24P (io), 22 I/O, VREF 6, L24N (io), 23 I/O, L23P_YY (io), 24 I/O, L23N_YY (io), 26 I/O, L22P (io), 27 I/O, VREF 6, L22N (io), 28 I/O (io), 29 I/O, VREF 6 (io), 30 I/O (io), 31 I/O, L21P_YY (io), 32 I/O, L21N_YY (io), 38 I/O, L20N_YY (io), 39 I/O, L20P_YY (io), 40 I/O (io), 41 I/O, VREF 5 (io), 42 I/O (io), 43 I/O, VREF 5, L19N_YY (io), 44 I/O, L19P_YY (io), 47 I/O, L18N_YY (io), 48 I/O, L18P_YY (io), 49 I/O, VREF 5 (io), 50 I/O (DLL), L17N (io), 52 GCK1, I (in), 55 GCK0, I (in), 56 I/O (DLL), L17P (io), 57 I/O (io), 58 I/O, VREF 4 (io), 59 I/O, L16N_YY (io), 60 I/O, L16P_YY (io), 63 I/O, L15N_YY (io), 64 I/O, VREF 4, L15P_YY (io), 65 I/O (io), 66 I/O, VREF 4 (io), 67 I/O (io), 68 I/O, L14N_YY (io), 69 I/O, L14P_YY (io), 75 I/O (D7), L13P_YY (io), 76 I/O (io), 77 I/O, VREF 3 (io), 78 I/O (io), 79 I/O, VREF 3, L12N (io), 80 I/O (D6), L12P (io), 82 I/O (D5), L11N_YY (io), 83 I/O, L11P_YY (io), 84 I/O (io), 85 I/O, VREF 3, L10N (io), 86 I/O (D4), L10P (io), 87 I/O (io), 89 I/O (TRDY) (io), 92 I/O (IRDY) (io), 93 I/O (io), 94 I/O (D3), L9N (io), 95 I/O, VREF 2, L9P (io), 96 I/O (io), 97 I/O, L8N_YY (io), 98 I/O (D2), L8P_YY (io), 100 I/O (D1), L7N (io), 101 I/O, VREF 2, L7P (io), 102 I/O (io), 103 I/O, VREF 2 (io), 104 I/O (io), 106 I/O (DOUT, BUSY), L6P_YY (io), 112 I/O (~{CS}), L5P_YY (io), 113 I/O (~{WRITE}), L5N_YY (io), 114 I/O (io), 115 I/O, VREF 1 (io), 116 I/O (io), 117 I/O, VREF 1, L4P_YY (io), 118 I/O, L4N_YY (io), 121 I/O, L3P_YY (io), 122 I/O, L3N_YY (io), 123 I/O, VREF 1 (io), 124 I/O (io), 125 I/O (DLL), L2P (io), 126 GCK2, I (in), 129 GCK3, I (in), 131 I/O (DLL), L2N (io), 132 I/O, VREF 0 (io), 133 I/O, L1P_YY (io), 134 I/O, L1N_YY (io), 137 I/O, L0P_YY (io), 138 I/O, VREF 0, L0N_YY (io), 139 I/O (io), 140 I/O, VREF 0 (io), 141 I/O (io), 142 I/O (io)
part B pins: 2 TMS (in), 33 M1 (in), 35 M0 (in), 37 M2 (in), 71 DONE (io), 73 PROGRAM (in), 74 ~{INIT} (io), 105 DIN (io), 107 CCLK (io), 109 TDO (out), 111 TDI (in), 143 TCK (in)
part C pins: 1 GND (power), 9 GND (power), 16 GND (power), 17 VCCO (power), 19 VCCINT (power), 25 GND (power), 34 GND (power), 36 VCCO (power), 45 GND (power), 46 VCCINT (power), 51 VCCINT (power), 53 VCCO (power), 54 GND (power), 61 VCCINT (power), 62 GND (power), 70 GND (power), 72 VCCO (power), 81 GND (power), 88 VCCINT (power), 90 VCCO (power), 91 GND (power), 99 GND (power), 108 VCCO (power), 110 GND (power), 119 GND (power), 120 VCCINT (power), 127 GND (power), 128 VCCO (power), 130 VCCINT (power), 135 VCCINT (power), 136 GND (power), 144 VCCO (power)

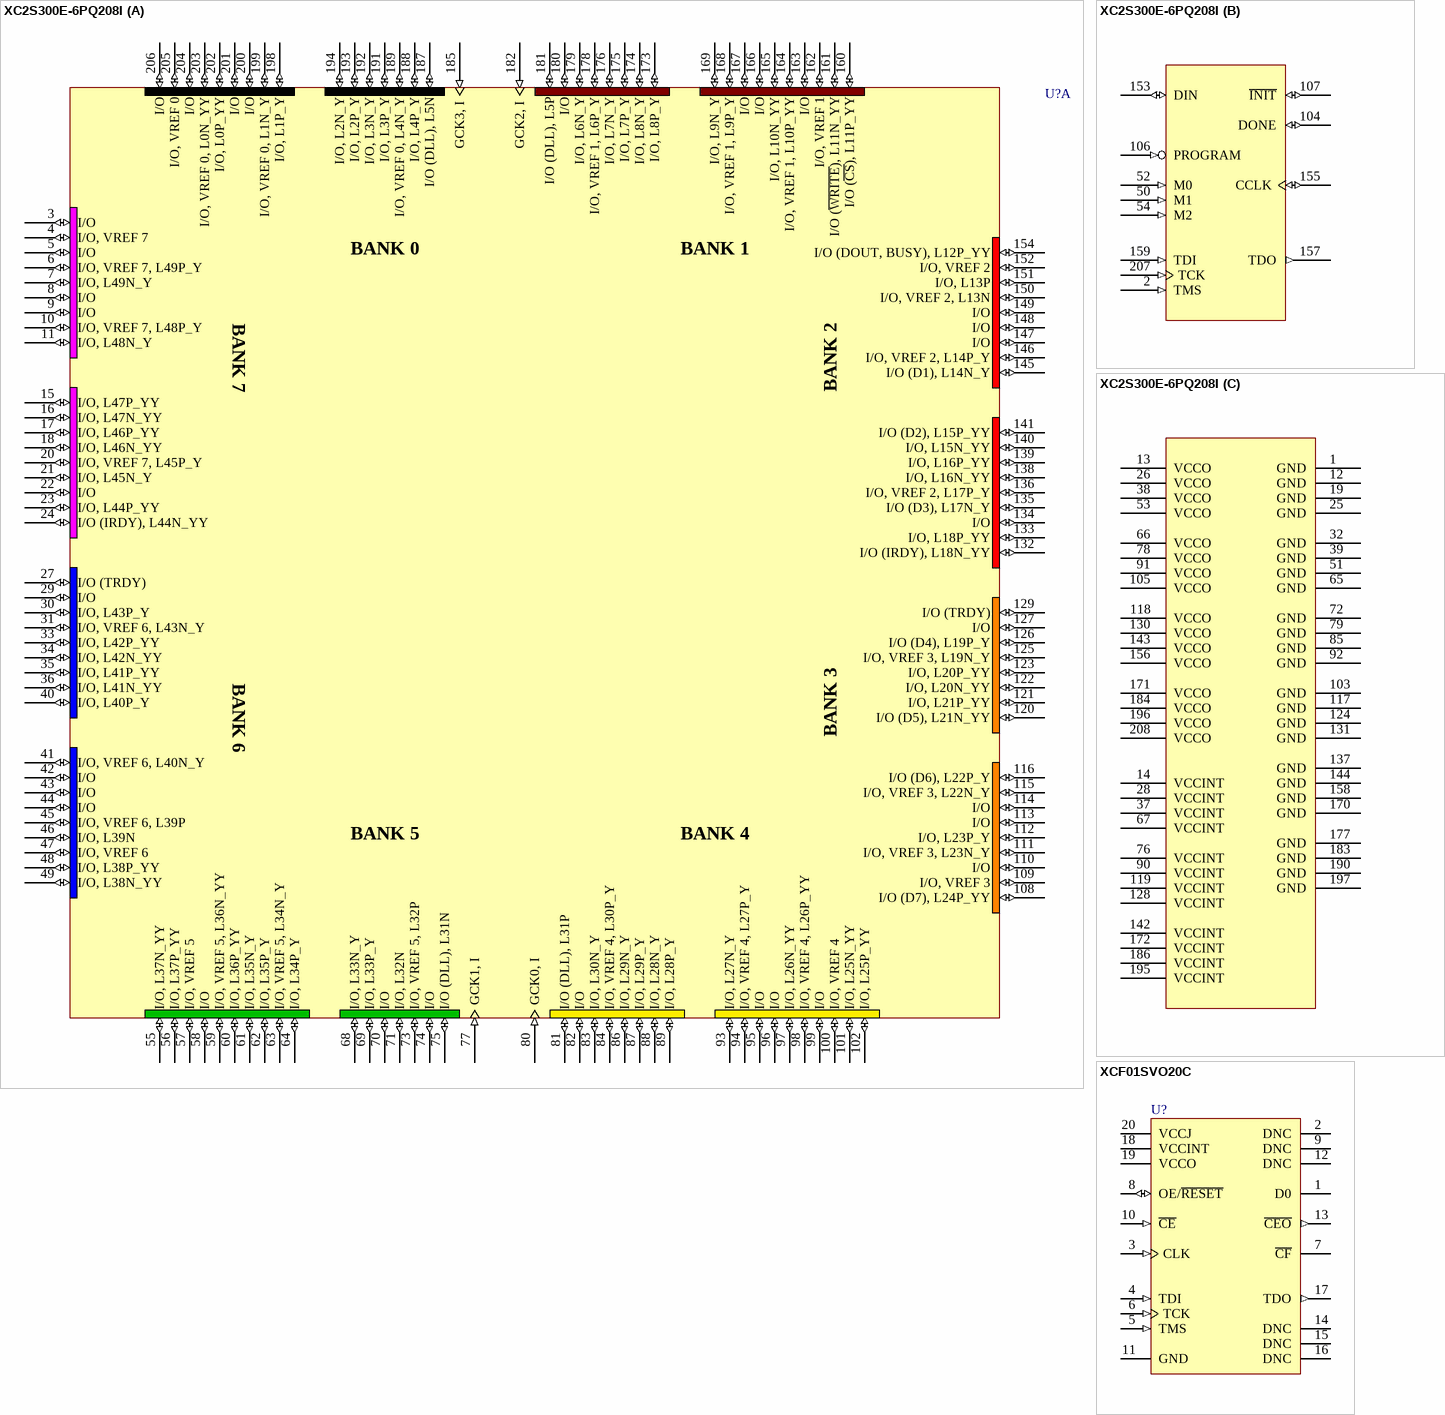
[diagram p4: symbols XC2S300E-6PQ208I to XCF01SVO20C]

## XC2S300E-6PQ208I
designator U?
Spartan-IIE 1.8V FPGA, 208-Pin PQFP, Standard Performance, Industrial Grade; PackageDocument: ver1.1, Oct-2002
footprint F-QFP28x28-G208/P.5N (208-Pin Plastic Quad Flat Pack (PQ208))
pcadlib F-QFP28x28-G208/P.5N (208-Pin Plastic Quad Flat Pack (PQ208))
3D model XC2S300E-PQ208 (208-Pin Plastic Quad Flat Pack (PQ208))
signal-integrity model XC2S300E_PQ208 (Spartan-IIE)
part A pins: 3 I/O (io), 4 I/O, VREF 7 (io), 5 I/O (io), 6 I/O, VREF 7, L49P_Y (io), 7 I/O, L49N_Y (io), 8 I/O (io), 9 I/O (io), 10 I/O, VREF 7, L48P_Y (io), 11 I/O, L48N_Y (io), 15 I/O, L47P_YY (io), 16 I/O, L47N_YY (io), 17 I/O, L46P_YY (io), 18 I/O, L46N_YY (io), 20 I/O, VREF 7, L45P_Y (io), 21 I/O, L45N_Y (io), 22 I/O (io), 23 I/O, L44P_YY (io), 24 I/O (IRDY), L44N_YY (io), 27 I/O (TRDY) (io), 29 I/O (io), 30 I/O, L43P_Y (io), 31 I/O, VREF 6, L43N_Y (io), 33 I/O, L42P_YY (io), 34 I/O, L42N_YY (io), 35 I/O, L41P_YY (io), 36 I/O, L41N_YY (io), 40 I/O, L40P_Y (io), 41 I/O, VREF 6, L40N_Y (io), 42 I/O (io), 43 I/O (io), 44 I/O (io), 45 I/O, VREF 6, L39P (io), 46 I/O, L39N (io), 47 I/O, VREF 6 (io), 48 I/O, L38P_YY (io), 49 I/O, L38N_YY (io), 55 I/O, L37N_YY (io), 56 I/O, L37P_YY (io), 57 I/O, VREF 5 (io), 58 I/O (io), 59 I/O, VREF 5, L36N_YY (io), 60 I/O, L36P_YY (io), 61 I/O, L35N_Y (io), 62 I/O, L35P_Y (io), 63 I/O, VREF 5, L34N_Y (io), 64 I/O, L34P_Y (io), 68 I/O, L33N_Y (io), 69 I/O, L33P_Y (io), 70 I/O (io), 71 I/O, L32N (io), 73 I/O, VREF 5, L32P (io), 74 I/O (io), 75 I/O (DLL), L31N (io), 77 GCK1, I (in), 80 GCK0, I (in), 81 I/O (DLL), L31P (io), 82 I/O (io), 83 I/O, L30N_Y (io), 84 I/O, VREF 4, L30P_Y (io), 86 I/O, L29N_Y (io), 87 I/O, L29P_Y (io), 88 I/O, L28N_Y (io), 89 I/O, L28P_Y (io), 93 I/O, L27N_Y (io), 94 I/O, VREF 4, L27P_Y (io), 95 I/O (io), 96 I/O (io), 97 I/O, L26N_YY (io), 98 I/O, VREF 4, L26P_YY (io), 99 I/O (io), 100 I/O, VREF 4 (io), 101 I/O, L25N_YY (io), 102 I/O, L25P_YY (io), 108 I/O (D7), L24P_YY (io), 109 I/O, VREF 3 (io), 110 I/O (io), 111 I/O, VREF 3, L23N_Y (io), 112 I/O, L23P_Y (io), 113 I/O (io), 114 I/O (io), 115 I/O, VREF 3, L22N_Y (io), 116 I/O (D6), L22P_Y (io), 120 I/O (D5), L21N_YY (io), 121 I/O, L21P_YY (io), 122 I/O, L20N_YY (io), 123 I/O, L20P_YY (io), 125 I/O, VREF 3, L19N_Y (io), 126 I/O (D4), L19P_Y (io), 127 I/O (io), 129 I/O (TRDY) (io), 132 I/O (IRDY), L18N_YY (io), 133 I/O, L18P_YY (io), 134 I/O (io), 135 I/O (D3), L17N_Y (io), 136 I/O, VREF 2, L17P_Y (io), 138 I/O, L16N_YY (io), 139 I/O, L16P_YY (io), 140 I/O, L15N_YY (io), 141 I/O (D2), L15P_YY (io), 145 I/O (D1), L14N_Y (io), 146 I/O, VREF 2, L14P_Y (io), 147 I/O (io), 148 I/O (io), 149 I/O (io), 150 I/O, VREF 2, L13N (io), 151 I/O, L13P (io), 152 I/O, VREF 2 (io), 154 I/O (DOUT, BUSY), L12P_YY (io), 160 I/O (~{CS}), L11P_YY (io), 161 I/O (~{WRITE}), L11N_YY (io), 162 I/O, VREF 1 (io), 163 I/O (io), 164 I/O, VREF 1, L10P_YY (io), 165 I/O, L10N_YY (io), 166 I/O (io), 167 I/O (io), 168 I/O, VREF 1, L9P_Y (io), 169 I/O, L9N_Y (io), 173 I/O, L8P_Y (io), 174 I/O, L8N_Y (io), 175 I/O, L7P_Y (io), 176 I/O, L7N_Y (io), 178 I/O, VREF 1, L6P_Y (io), 179 I/O, L6N_Y (io), 180 I/O (io), 181 I/O (DLL), L5P (io), 182 GCK2, I (in), 185 GCK3, I (in), 187 I/O (DLL), L5N (io), 188 I/O, L4P_Y (io), 189 I/O, VREF 0, L4N_Y (io), 191 I/O, L3P_Y (io), 192 I/O, L3N_Y (io), 193 I/O, L2P_Y (io), 194 I/O, L2N_Y (io), 198 I/O, L1P_Y (io), 199 I/O, VREF 0, L1N_Y (io), 200 I/O (io), 201 I/O (io), 202 I/O, L0P_YY (io), 203 I/O, VREF 0, L0N_YY (io), 204 I/O (io), 205 I/O, VREF 0 (io), 206 I/O (io)
part B pins: 2 TMS (in), 50 M1 (in), 52 M0 (in), 54 M2 (in), 104 DONE (io), 106 PROGRAM (in), 107 ~{INIT} (io) "I/O (I\N\I\T\), L24N_YY", 153 DIN (io) "I/O (DIN, D0), L12N_YY", 155 CCLK (io), 157 TDO (out), 159 TDI (in), 207 TCK (in)
part C pins: 1 GND (power), 12 GND (power), 13 VCCO (power), 14 VCCINT (power), 19 GND (power), 25 GND (power), 26 VCCO (power), 28 VCCINT (power), 32 GND (power), 37 VCCINT (power), 38 VCCO (power), 39 GND (power), 51 GND (power), 53 VCCO (power), 65 GND (power), 66 VCCO (power), 67 VCCINT (power), 72 GND (power), 76 VCCINT (power), 78 VCCO (power), 79 GND (power), 85 GND (power), 90 VCCINT (power), 91 VCCO (power), 92 GND (power), 103 GND (power), 105 VCCO (power), 117 GND (power), 118 VCCO (power), 119 VCCINT (power), 124 GND (power), 128 VCCINT (power), 130 VCCO (power), 131 GND (power), 137 GND (power), 142 VCCINT (power), 143 VCCO (power), 144 GND (power), 156 VCCO (power), 158 GND (power), 170 GND (power), 171 VCCO (power), 172 VCCINT (power), 177 GND (power), 183 GND (power), 184 VCCO (power), 186 VCCINT (power), 190 GND (power), 195 VCCINT (power), 196 VCCO (power), 197 GND (power), 208 VCCO (power)

## XCF01SVO20C
designator U?
XCF00S Series, Platform Flash In-System Programmable Configuration 3.3V PROM, 1-Megabit, Commercial Grade
footprint VO20 (20-Pin Thin Small-Outline Package (VO20))
pcadlib VO20 (20-Pin Thin Small-Outline Package (VO20))
pins: 1 D0 (hiz) "Serial Data Output, for configuring an FPGA in serial mode.", 2 DNC "Leave Unconnected.", 3 CLK (in) "Configuration Clock Input.", 4 TDI (in) "JTAG Serial Data Input.", 5 TMS (in) "JTAG Mode Select Input.", 6 TCK (in) "JTAG Test Clock Input.", 7 ~{CF} (oc) "Configuration Pulse (Open-Drain Output).", 8 OE/~{RESET} (io) "Output Enable/Reset (Open-Drain I/O).", 9 DNC "Leave Unconnected.", 10 ~{CE} (in) "Chip Enable Input.", 11 GND (power) "Ground", 12 DNC "Leave Unconnected.", 13 ~{CEO} (out) "Chip Enable Output, connects to the CE input of the next PROM in the chain.", 14 DNC "Leave Unconnected.", 15 DNC "Leave Unconnected.", 16 DNC "Leave Unconnected.", 17 TDO (out) "JTAG Serial Data Output.", 18 VCCINT (power) "+3.3V Supply for internal logic.", 19 VCCO (power) "+3.3V, 2.5V, or 1.8V I/O Supply.", 20 VCCJ (power) "+3.3V or 2.5V JTAG Signals I/O Supply."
